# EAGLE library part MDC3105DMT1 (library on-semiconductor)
Integrated Relay, Inductive Load Driver Sopurce: U6 OnSemi Inductive Load Driver MDC3105-D.PDF
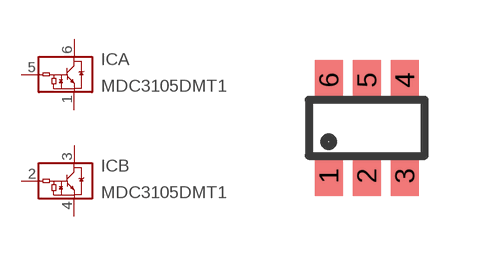
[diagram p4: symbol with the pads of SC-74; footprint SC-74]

Designator prefix IC; gates A=NPN-DRIVER B=NPN-DRIVER

## MDC3105DMT1 (MPN: MDC3105DMT1G; OC_FARNELL: unknown; OC_NEWARK: 04R7836)  [SC-74]
1  A:GND  pas
2  B:VIN  pas
3  B:VOUT  pas
4  B:GND  pas
5  A:VIN  pas
6  A:VOUT  pas

## Footprint SC-74 (pad centres in mm)
Small Outline Transistor; 6 leads SC-74 CASE 318F-05 ISSUE M Source: U6 OnSemi Inductive Load Driver MDC3105-D.PDF
smd 0.7 x 1: 1 -0.95,-1.2; 2 0,-1.2; 3 0.95,-1.2; 4 0.95,1.2; 5 0,1.2; 6 -0.95,1.2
